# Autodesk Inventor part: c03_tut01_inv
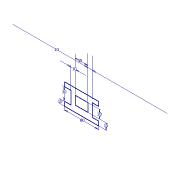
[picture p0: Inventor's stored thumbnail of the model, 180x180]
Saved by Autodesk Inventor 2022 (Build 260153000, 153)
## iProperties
Created: 2017-04
Part Number: c03_tut01_inv
Material: Generic
Document SubType Name: Modeling
Designer: CADCIM 00
Density: 1 g/cm^3
Appearance: Default
Author: CADCIM 00
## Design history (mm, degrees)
sketch "Sketch1"
  geometry: 1 further point
sketch "Sketch2"
  geometry: L1 (0, 0)-(0, 10); L2 (0, 10)-(-15, 10); L3 (-15, 10)-(-15, 40); L4 (-15, 40)-(0, 40); L5 (0, 40)-(0, 50); L6 (0, 50)-(-80, 50); L7 (-80, 50)-(-80, 40); L8 (-80, 40)-(-65, 40); L9 (-65, 40)-(-65, 10); L10 (-65, 10)-(-80, 10); L11 (-80, 0)-(0, 0); L12 (-80, 10)-(-80, 0); L13 (-25, 35)-(-55, 35); L14 (-55, 35)-(-55, 15); L15 (-55, 15)-(-25, 15); L16 (-25, 15)-(-25, 35)
  constraints: 32 end point, 8 perpendicular, 8 point on line, 3 parallel, 2 collinear, 1 horizontal, 1 vertical
  dimensions: "d0" = 80 distance of L11.start L1.start; "d1" = 10 distance of L1.start L1.end; "d2" = 30 distance of L2.end L3.end; "d3" = 10 distance between parallel lines of L16 L3; "d4" = 10 distance between parallel lines of L9 L14; "d5" = 15 distance between parallel lines of L15 L11; "d6" = 20 distance of L13.end L14.end; "d7" = 30 distance of L13.start L13.end
